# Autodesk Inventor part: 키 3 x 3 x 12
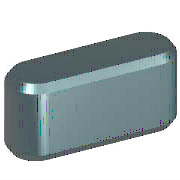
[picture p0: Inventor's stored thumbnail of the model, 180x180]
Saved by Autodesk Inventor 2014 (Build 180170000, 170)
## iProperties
Created: 2012-02
Part Number: 키 3 x 3 x 12
Material: 강철, 연강
Description: 키 및 해당 키홈
Document SubType Name: Modeling
Standard: KS B 1311
Designer: mduedu
Standards Organization: KS
Language: ko-KR
Size Designation: 3 x 3 x 12
Categories: <MemberInstance><Categories><Category DisplayName="샤프트 부품" InternalName="7f7aeb1f-a693-4053-b835-cee3144e0d98" Mnemonic="SHFT"><Category DisplayName="키" Interna
Density: 1 g/cm^3
Appearance: 노란색
IsCustomPart: 1
Author: mduedu
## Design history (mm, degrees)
workplane "Work Plane1"
workplane "Work Plane2"
sketch "스케치1"
  geometry: L1 (1.5, 1.5)-(10.5, 1.5); L2 (10.5, -1.5)-(1.5, -1.5); L3 (0, 9.4)-(0, -7.4) reference; L4 (-5, 0)-(30, 0) reference; L5 (12, 0)-(12, 7); A1 r 1.5 centre (1.5, 0) between (1.5, 1.5) and (1.5, -1.5); A2 r 1.5 centre (10.5, 0) between (10.5, -1.5) and (10.5, 1.5)
  constraints: 6 end point, 5 point on circle, 4 tangent, 3 point on line, 2 centre point, 1 horizontal, 1 parallel, 1 perpendicular
  dimensions: "d0" = 1.5 radius of A1 (= 0.5 x PB); "d13" = 1.5 radius of A2 (= 0.5 x PB); "d14" = 12 distance between parallel lines of L5 L3 (= NLG)
extrude "본체1" new body sketch "스케치1" taper "d3" = 0 deg; stored distance "d4" = 10
workplane "Work Plane3"
body "Solid1"
chamfer "모따기1" distance "d8" = 0.25 (= PHH); stored, may be unused: second distance "d9" = 0.25 (= PHH), angle "d15" = 45 deg
other parameters: "d1" = -1.8 (= -PNT), "d2" = 1.2 (= PH - PNT), "NLG" = 12 [user parameter; used in 3 equation terms], "PB" = 3 [user parameter; used in 2 equation terms], "PNT" = 1.8 [user parameter; used in 2 equation terms], "PH" = 3 [user parameter; used in 1 equation term], "PHH" = 0.25 [user parameter; used in 2 equation terms], "d10" = 0, "d16" = 0, "d17" = 0, "d18" = 0, "WDMIN" = 8 [user parameter], "PLB2" = 12 (= NLG) [user parameter], "PLB1" = 12 (= NLG) [user parameter], "RR" = 0.08 [user parameter], "PUEB" = 1.4 [user parameter]
